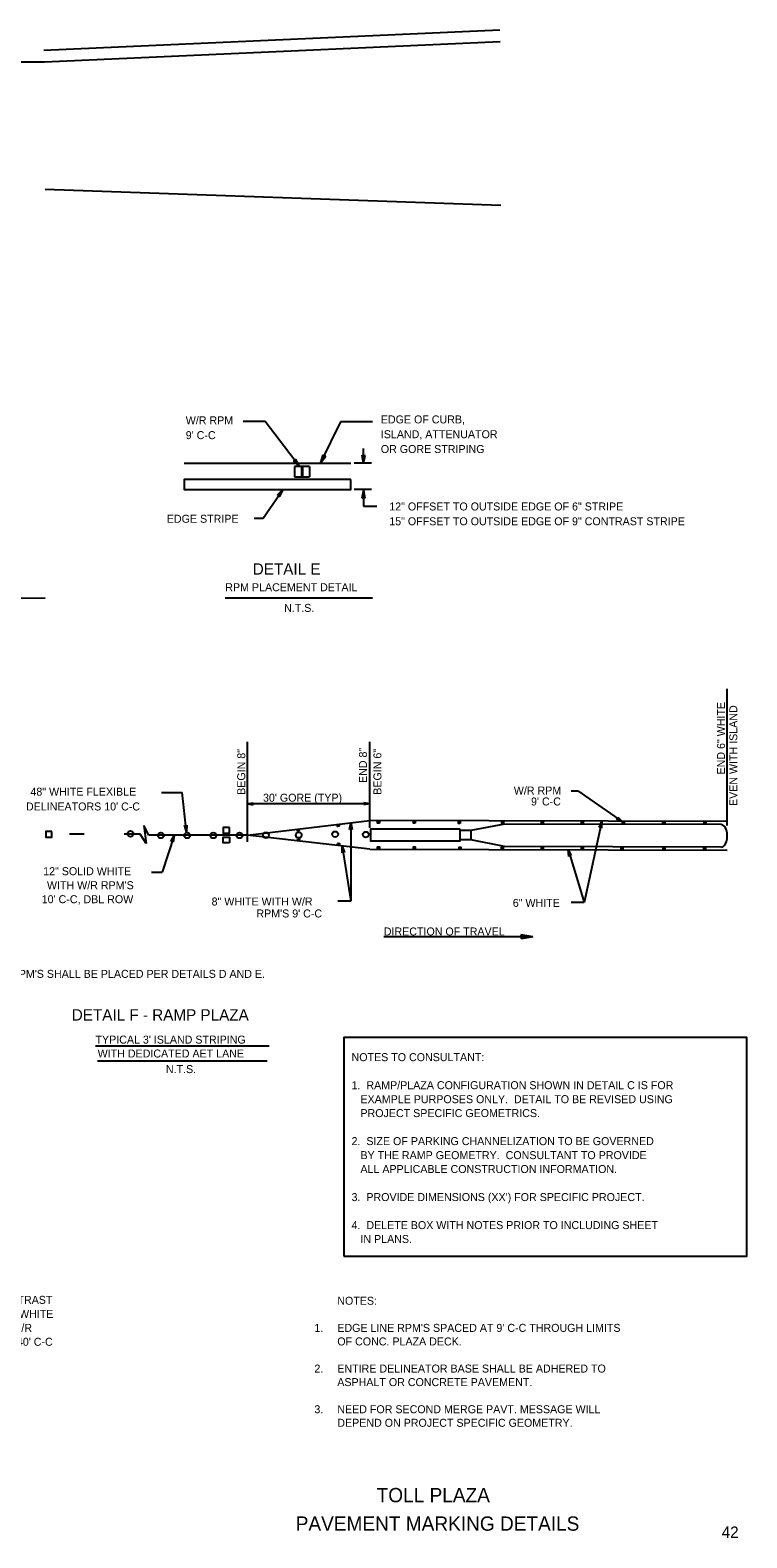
# Model space of a CAD drawing. Extents: x 583689 to 590775, y 1496016 to 1497365.
# Drawn here: x 588186 to 588815, y 1496041 to 1497365 of the extents above; entities that cross this region are included whole.
import ezdxf

# ---------------------------------------------------------------- set-up
doc = ezdxf.new("R2010")
doc.units = 0
for name, color, linetype in [('10', 7, 'Continuous'), ('11', 7, 'Continuous'), ('21', 7, 'Continuous'), ('32', 7, 'Continuous'), ('42', 7, 'Continuous'), ('5', 7, 'Continuous'), ('50', 7, 'Continuous'), ('52', 7, 'Continuous'), ('6', 7, 'Continuous'), ('TextAlert', 7, 'Continuous'), ('TextMisc', 7, 'Continuous'), ('TextNotes', 7, 'Continuous'), ('TextShtNo', 7, 'Continuous')]:
    doc.layers.add(name, color=color, linetype=linetype)

msp = doc.modelspace()

# ---------------------------------------------------------------- linework, layer by layer
at = {"layer": '10'}
for p, q in [((588572.6, 1496662.2), (588562.9, 1496662.2)), ((588602.2, 1496667.9), (588572.6, 1496662.2)), ((588572.6, 1496662.2), (588572.6, 1496654)), ((588792.3, 1496667.4), (588602.2, 1496667.9)), ((588572.6, 1496654), (588562.9, 1496654)), ((588602.1, 1496648.2), (588572.6, 1496654)), ((588792.3, 1496647.7), (588602.1, 1496648.2))]:
    msp.add_line(p, q, dxfattribs=at)
msp.add_lwpolyline([(588562.9, 1496663.6), (588562.9, 1496653), (588484.9, 1496653), (588484.9, 1496663.6)], close=True, dxfattribs=at)
msp.add_ellipse((588792.3, 1496657.5), major_axis=(0, 9.84), ratio=0.545749, start_param=3.141593, end_param=6.283306, dxfattribs=at)
at = {"layer": '11'}
for p, q in [((588376.6, 1496658.2), (588484, 1496670.9)), ((588797.6, 1496670.1), (588484, 1496670.9)), ((588484, 1496645.8), (588376.6, 1496658.2)), ((588484, 1496645.8), (588797.6, 1496645))]:
    msp.add_line(p, q, dxfattribs=at)
for points in [[(588422, 1496661.7), (588420.5, 1496661.5), (588420.4, 1496663), (588421.8, 1496663.1)], [(588457.1, 1496665.9), (588455.7, 1496665.8), (588455.6, 1496667.2), (588457, 1496667.4)], [(588492.4, 1496668.8), (588490.9, 1496668.8), (588490.9, 1496670.4), (588492.4, 1496670.4)], [(588523.8, 1496668.7), (588522.4, 1496668.7), (588522.4, 1496670.3), (588523.8, 1496670.3)], [(588563.4, 1496668.5), (588562, 1496668.5), (588562, 1496670.1), (588563.4, 1496670.1)], [(588601.3, 1496668.4), (588599.9, 1496668.4), (588599.9, 1496670), (588601.3, 1496670)], [(588636.1, 1496668.5), (588634.6, 1496668.5), (588634.6, 1496670.1), (588636.1, 1496670.1)], [(588671.3, 1496668.4), (588669.8, 1496668.4), (588669.8, 1496670), (588671.3, 1496670)], [(588707.3, 1496668.1), (588705.8, 1496668.1), (588705.8, 1496669.8), (588707.3, 1496669.8)], [(588742.8, 1496668.1), (588741.3, 1496668.1), (588741.3, 1496669.8), (588742.8, 1496669.8)], [(588778.9, 1496668.1), (588777.4, 1496668.1), (588777.4, 1496669.7), (588778.9, 1496669.7)], [(588422, 1496653.3), (588420.6, 1496653.4), (588420.8, 1496654.9), (588422.2, 1496654.7)], [(588457.2, 1496649.4), (588455.8, 1496649.6), (588455.9, 1496651), (588457.4, 1496650.8)], [(588492.4, 1496646.3), (588490.9, 1496646.3), (588490.9, 1496647.9), (588492.4, 1496647.9)], [(588523.7, 1496646.2), (588522.3, 1496646.2), (588522.3, 1496647.8), (588523.7, 1496647.8)], [(588564, 1496646.1), (588562.5, 1496646.1), (588562.5, 1496647.7), (588564, 1496647.7)], [(588601.2, 1496646.1), (588599.7, 1496646.1), (588599.7, 1496647.7), (588601.2, 1496647.7)], [(588636.1, 1496645.8), (588634.6, 1496645.8), (588634.6, 1496647.5), (588636.1, 1496647.5)], [(588671.3, 1496645.5), (588669.8, 1496645.5), (588669.8, 1496647.2), (588671.3, 1496647.2)], [(588706.1, 1496645.7), (588704.7, 1496645.7), (588704.7, 1496647.3), (588706.1, 1496647.3)], [(588742.9, 1496645.3), (588741.4, 1496645.3), (588741.4, 1496646.9), (588742.9, 1496646.9)], [(588778.7, 1496645.4), (588777.3, 1496645.4), (588777.3, 1496647), (588778.7, 1496647)]]:
    msp.add_lwpolyline(points, close=True, dxfattribs=at)
for centre in [(588274, 1496659.3), (588300.7, 1496657.9), (588323.7, 1496657.9), (588346.7, 1496657.9), (588369.7, 1496657.9), (588392.9, 1496658), (588421.6, 1496658.2), (588453.6, 1496658.9), (588480.5, 1496658.6)]:
    msp.add_circle(centre, 2.54, dxfattribs=at)
at = {"layer": '21'}
for p, q in [((588425, 1496981.6), (588425, 1496972.6)), ((588797.6, 1496666.7), (588797.6, 1496786.5)), ((588376.7, 1496652.3), (588376.6, 1496740)), ((588484, 1496664.7), (588484, 1496740)), ((588660.6, 1496696.9), (588666.5, 1496696.9)), ((588666.5, 1496696.9), (588705.8, 1496669.8)), ((588376.6, 1496685.6), (588381.8, 1496686.6)), ((588376.6, 1496685.6), (588381.6, 1496686.1)), ((588484, 1496685.6), (588376.6, 1496685.6)), ((588376.6, 1496685.6), (588381.8, 1496684.7)), ((588376.6, 1496685.6), (588381.6, 1496685.2)), ((588381.8, 1496686.6), (588381.4, 1496685.7)), ((588381.4, 1496685.7), (588381.8, 1496684.7)), ((588484, 1496685.6), (588478.7, 1496686.4)), ((588479.1, 1496685.5), (588478.7, 1496686.4)), ((588484, 1496685.6), (588478.8, 1496684.6)), ((588478.8, 1496684.6), (588479.1, 1496685.5)), ((588484, 1496685.6), (588478.9, 1496685.9)), ((588484, 1496685.6), (588479, 1496685.1)), ((588467.4, 1496668.9), (588467.4, 1496600.2)), ((588687.5, 1496670.3), (588672.2, 1496599.1)), ((588459.9, 1496648.6), (588467.4, 1496600.2)), ((588658, 1496645.4), (588672.2, 1496599.1)), ((588467.4, 1496600.2), (588455.9, 1496600.2)), ((588672.2, 1496599.1), (588660.7, 1496599.1)), ((588627.2, 1496569), (588523.5, 1496569)), ((588627.2, 1496569), (588616.7, 1496570.7)), ((588617.6, 1496568.9), (588616.7, 1496570.7)), ((588627.2, 1496569), (588616.8, 1496567)), ((588616.8, 1496567), (588617.6, 1496568.9)), ((588627.2, 1496569), (588617.2, 1496569.7)), ((588627.2, 1496569), (588617.2, 1496568)), ((588243.3, 1496473.1), (588395.8, 1496473.1)), ((588245.2, 1496460.1), (588393.9, 1496460.1))]:
    msp.add_line(p, q, dxfattribs=at)
at = {"layer": '32'}
for p, q in [((588290.1, 1496658.2), (588285.7, 1496666.6)), ((588285.7, 1496666.6), (588287.7, 1496650.9)), ((588233.4, 1496658.9), (588220.5, 1496658.9)), ((588282.5, 1496658.9), (588268.4, 1496658.9)), ((588287.7, 1496650.9), (588282.5, 1496658.9)), ((588376.6, 1496658.2), (588290.1, 1496658.2))]:
    msp.add_line(p, q, dxfattribs=at)
for points in [[(588205.1, 1496661.4), (588199.7, 1496661.4), (588199.7, 1496656.5), (588205.1, 1496656.5)], [(588360.8, 1496664.8), (588355.4, 1496664.8), (588355.4, 1496659.8), (588360.8, 1496659.8)], [(588360.8, 1496651.5), (588355.4, 1496651.5), (588355.4, 1496656.4), (588360.8, 1496656.4)]]:
    msp.add_lwpolyline(points, close=True, dxfattribs=at)
at = {"layer": '42'}
msp.add_line((588598, 1497364.6), (588198.1, 1497346.9), dxfattribs=at)
at = {"layer": '5'}
for p, q in [((588198.6, 1497336.9), (588598.4, 1497354.6)), ((587948.5, 1497335.8), (588198.6, 1497336.9)), ((588599.1, 1497210.7), (588199.1, 1497224.9)), ((588199.1, 1496866), (586110.2, 1496856.7))]:
    msp.add_line(p, q, dxfattribs=at)
at = {"layer": '50'}
for p, q in [((588392.1, 1497021.1), (588373, 1497021.1)), ((588422.2, 1496981.6), (588392.1, 1497021.1)), ((588458.4, 1497020.8), (588441, 1496985.9)), ((588486.3, 1497020.9), (588458.4, 1497020.8)), ((588441, 1496985.1), (588443.1, 1496991.9)), ((588441, 1496985.1), (588443.6, 1496991.3)), ((588444, 1496990.8), (588443.1, 1496991.9)), ((588478.5, 1496984.4), (588477.4, 1496991.5)), ((588478.6, 1496990.9), (588477.4, 1496991.5)), ((588478.5, 1496984.4), (588478, 1496991.2)), ((588478.5, 1496984.4), (588478.5, 1496997.6)), ((588478.5, 1496984.4), (588479.9, 1496991.4)), ((588478.5, 1496984.4), (588479.2, 1496991.2)), ((588479.9, 1496991.4), (588478.6, 1496990.9)), ((588321, 1496984.5), (588467.5, 1496984.5)), ((588418.3, 1496986.8), (588417, 1496986.5)), ((588422.2, 1496981.6), (588417, 1496986.5)), ((588422.2, 1496981.6), (588417.7, 1496986.7)), ((588418, 1496981.6), (588418, 1496972.6)), ((588431, 1496981.6), (588418, 1496981.6)), ((588419, 1496988), (588418.3, 1496986.8)), ((588422.2, 1496981.6), (588418.7, 1496987.4)), ((588422.2, 1496981.6), (588419, 1496988)), ((588424, 1496981.6), (588424, 1496972.6)), ((588431, 1496981.6), (588431, 1496972.6)), ((588441, 1496985.1), (588444.6, 1496990.8)), ((588441, 1496985.1), (588445.3, 1496990.7)), ((588445.3, 1496990.7), (588444, 1496990.8)), ((588485.6, 1496984.5), (588470.3, 1496984.5)), ((588418, 1496972.6), (588431, 1496972.6)), ((588390.3, 1496936.4), (588408.1, 1496961.9)), ((588485.6, 1496961.4), (588470.3, 1496961.4)), ((588478.5, 1496960.9), (588477.1, 1496953.9)), ((588477.1, 1496953.9), (588478.4, 1496954.5)), ((588478.5, 1496960.9), (588477.8, 1496954.2)), ((588478.4, 1496954.5), (588479.6, 1496953.9)), ((588478.5, 1496961.4), (588478.5, 1496946.8)), ((588478.5, 1496960.9), (588479.6, 1496953.9)), ((588478.5, 1496960.9), (588479, 1496954.2)), ((588478.5, 1496946.8), (588490.3, 1496946.8)), ((588382.6, 1496936.4), (588390.3, 1496936.4)), ((588357.2, 1496866.4), (588486.3, 1496866.4)), ((588301.2, 1496695.5), (588319.3, 1496695.5)), ((588323.1, 1496661.1), (588319.3, 1496695.5)), ((588312.2, 1496657.9), (588301.8, 1496625.6)), ((588292.5, 1496625.6), (588301.8, 1496625.6))]:
    msp.add_line(p, q, dxfattribs=at)
msp.add_lwpolyline([(588467.5, 1496970.4), (588321, 1496970.4), (588321, 1496961.4), (588467.5, 1496961.4)], close=True, dxfattribs=at)
at = {"layer": '52'}
for p, q in [((588701.4, 1496672.8), (588701.7, 1496673.9)), ((588701.7, 1496673.9), (588705.8, 1496669.8)), ((588323.1, 1496661.1), (588321.4, 1496666.8)), ((588321.4, 1496666.8), (588322.5, 1496666.5)), ((588322.5, 1496666.5), (588323.6, 1496667)), ((588323.6, 1496667), (588323.1, 1496661.1)), ((588466.3, 1496663.1), (588467.4, 1496668.9)), ((588467.4, 1496663.6), (588466.3, 1496663.1)), ((588467.4, 1496668.9), (588468.5, 1496663.1)), ((588468.5, 1496663.1), (588467.4, 1496663.6)), ((588685.2, 1496664.9), (588687.5, 1496670.3)), ((588686.4, 1496665.1), (588685.2, 1496664.9)), ((588687.4, 1496664.4), (588686.4, 1496665.1)), ((588687.5, 1496670.3), (588687.4, 1496664.4)), ((588700.4, 1496672.1), (588701.4, 1496672.8)), ((588705.8, 1496669.8), (588700.4, 1496672.1)), ((588309.4, 1496652.7), (588312.2, 1496657.9)), ((588310.6, 1496652.8), (588309.4, 1496652.7)), ((588311.5, 1496652), (588310.6, 1496652.8)), ((588312.2, 1496657.9), (588311.5, 1496652)), ((588459.7, 1496642.7), (588459.9, 1496648.6)), ((588459.9, 1496648.6), (588461.9, 1496643)), ((588460.7, 1496643.3), (588459.7, 1496642.7)), ((588461.9, 1496643), (588460.7, 1496643.3)), ((588658, 1496645.4), (588660.7, 1496640.2)), ((588658.6, 1496639.5), (588658, 1496645.4)), ((588659.5, 1496640.2), (588658.6, 1496639.5)), ((588660.7, 1496640.2), (588659.5, 1496640.2))]:
    msp.add_line(p, q, dxfattribs=at)
msp.add_lwpolyline([(588408.1, 1496961.9), (588404.9, 1496955.3), (588404.2, 1496956.5), (588402.9, 1496956.8)], close=True, dxfattribs=at)
at = {"layer": 'TextAlert'}
msp.add_lwpolyline([(588461.1, 1496288.7), (588814.9, 1496288.7), (588814.9, 1496480.6), (588461.1, 1496480.6)], close=True, dxfattribs=at)
at = {"layer": 'TextShtNo'}
msp.add_line((588523.5, 1496569), (588496.3, 1496569), dxfattribs=at)

# ---------------------------------------------------------------- texts
at = {"layer": '21'}
for s, p in [('W/R RPM', (588610.4, 1496693.8)), ("30' GORE (TYP)", (588390.3, 1496687.5)), ("9' C-C", (588625.5, 1496684.2)), ('6" WHITE', (588609.5, 1496595.2)), ('DIRECTION OF TRAVEL', (588496.3, 1496570.1)), ('9" CONTRAST', (588142.9, 1496246.8)), ('BLACK/WHITE', (588142.9, 1496234.5)), ('WITH W/R', (588142.9, 1496222.2)), ("RPM'S 40' C-C", (588142.9, 1496210))]:
    msp.add_text(s, height=7, dxfattribs=at).set_placement(p)
at = {"layer": '50'}
for s, height, p in [('W/R RPM', 7, (588322.5, 1497018.7)), ('EDGE OF CURB,', 7, (588493.7, 1497019.5)), ("9' C-C", 7, (588322.5, 1497005.7)), ('ISLAND, ATTENUATOR', 7, (588493.7, 1497006.5)), ('OR GORE STRIPING', 7, (588493.7, 1496993.5)), ('12" OFFSET TO OUTSIDE EDGE OF 6" STRIPE ', 7, (588501.1, 1496943.1)), ('15" OFFSET TO OUTSIDE EDGE OF 9" CONTRAST STRIPE', 7, (588501.1, 1496930.1)), ('DETAIL E', 10, (588381.3, 1496886.7)), ("DELINEATORS 10' C-C ", 7, (588182.3, 1496679.8)), ('48" WHITE FLEXIBLE', 7, (588186.2, 1496692.8)), ('12" SOLID WHITE', 7, (588197.4, 1496623)), ("WITH W/R RPM'S", 7, (588200.7, 1496610.7)), ("10' C-C, DBL ROW", 7, (588196.1, 1496598.4)), ('8" WHITE WITH W/R', 7, (588345.2, 1496596.4)), ("RPM'S 9' C-C", 7, (588384.5, 1496585.9))]:
    msp.add_text(s, height=height, dxfattribs=at).set_placement(p)
for s, rotation, p in [('EDGE STRIPE', 0, (588305.9, 1496932.3)), ('RPM PLACEMENT DETAIL', 359.9987, (588357.2, 1496872.2)), ('N.T.S.', 0, (588408.8, 1496854.1)), ('END 6" WHITE', 90, (588795.7, 1496711.4)), ('EVEN WITH ISLAND', 90, (588806.5, 1496683.7)), ('BEGIN 8"', 90, (588374.7, 1496693.5)), ('END 8"', 90, (588481.5, 1496703.9)), ('BEGIN 6"', 90, (588494.2, 1496693.6))]:
    msp.add_text(s, height=7, rotation=rotation, dxfattribs=at).set_placement(p)
at = {"layer": '6'}
for s, height, p in [('DETAIL F - RAMP PLAZA', 10, (588222.5, 1496495.4)), ("TYPICAL 3' ISLAND STRIPING", 7, (588243.3, 1496475.2)), ('WITH DEDICATED AET LANE', 7, (588245.2, 1496463)), ('N.T.S.', 7, (588305.1, 1496449.3))]:
    msp.add_text(s, height=height, rotation=359.9987, dxfattribs=at).set_placement(p)
at = {"layer": 'TextAlert'}
for s, p in [('NOTES TO CONSULTANT:  ', (588468, 1496459.8)), ('1.  RAMP/PLAZA CONFIGURATION SHOWN IN DETAIL C IS FOR', (588468, 1496435.2)), ('   EXAMPLE PURPOSES ONLY.  DETAIL TO BE REVISED USING', (588468, 1496422.9)), ('   PROJECT SPECIFIC GEOMETRICS.', (588468, 1496410.7)), ('2.  SIZE OF PARKING CHANNELIZATION TO BE GOVERNED ', (588468, 1496386.1)), ('   BY THE RAMP GEOMETRY.  CONSULTANT TO PROVIDE ', (588468, 1496373.8)), ('   ALL APPLICABLE CONSTRUCTION INFORMATION.', (588468, 1496361.6)), ("3.  PROVIDE DIMENSIONS (XX') FOR SPECIFIC PROJECT.", (588468, 1496337)), ('4.  DELETE BOX WITH NOTES PRIOR TO INCLUDING SHEET', (588468, 1496312.4)), ('   IN PLANS.', (588468, 1496300.2))]:
    msp.add_text(s, height=7, dxfattribs=at).set_placement(p)
at = {"layer": 'TextMisc'}
for s, p in [('       TOLL PLAZA       ', (588457.5, 1496072.7)), ('PAVEMENT MARKING DETAILS', (588419, 1496047.7))]:
    msp.add_text(s, height=12.5, rotation=360, dxfattribs=at).set_placement(p)
at = {"layer": 'TextNotes'}
msp.add_text("  1.  RPM'S SHALL BE PLACED PER DETAILS D AND E.", height=7, dxfattribs=at).set_placement((588151, 1496532.9))
for s, p in [('NOTES:', (588455.5, 1496246)), ('1.', (588435.4, 1496222.2)), ("EDGE LINE RPM'S SPACED AT 9' C-C THROUGH LIMITS", (588455.5, 1496222.2)), ('OF CONC. PLAZA DECK.', (588455.5, 1496210.3)), ('2.  ', (588435.4, 1496186.5)), ('ENTIRE DELINEATOR BASE SHALL BE ADHERED TO', (588455.5, 1496186.5)), ('ASPHALT OR CONCRETE PAVEMENT.', (588455.5, 1496174.6)), ('3.', (588435.4, 1496150.8)), ('NEED FOR SECOND MERGE PAVT. MESSAGE WILL', (588455.5, 1496150.8)), ('DEPEND ON PROJECT SPECIFIC GEOMETRY.', (588455.5, 1496138.9))]:
    msp.add_text(s, height=7, rotation=0.0001, dxfattribs=at).set_placement(p)
at = {"layer": 'TextShtNo'}
msp.add_text('42', height=10, rotation=360, dxfattribs=at).set_placement((588792.8, 1496041.4))

doc.saveas('drawing.dxf')
